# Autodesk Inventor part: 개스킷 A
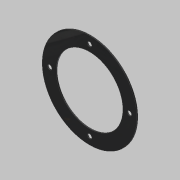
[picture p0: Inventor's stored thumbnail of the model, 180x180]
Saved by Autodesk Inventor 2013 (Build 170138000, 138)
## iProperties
Created: 2019-10
Part Number: 개스킷 A
Material: 고무
Document SubType Name: Modeling
Designer: mduedu
Density: 0.93 g/cm^3
Mass: 3.25402 g
Surface Area: 75.6338 cm^2
Volume: 3.49895 cm^3
Author: mduedu
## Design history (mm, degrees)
sketch "스케치1"
  geometry: C1 r 47.5 at (0, 0); C2 r 33.5 at (0, 0); 1 further point
  constraints: 2 centre point, 2 coincident
  dimensions: "d0" = 95 diameter of C1; "d1" = 67 diameter of C2
extrude "돌출1" new body sketch "스케치1" distance "d2" = 1; taper "d3" = 0 deg
sketch "스케치2" dims "d4" = 80
  geometry: C1 r 2.25 at (0, 40); 2 further points
  constraints: 2 vertical alignment, 1 centre point, 1 coincident, 2 other
  dimensions: "d5" = 4.5 diameter of C1
extrude "돌출2" cut sketch "스케치2" stored distance "d6" = 1; taper "d7" = 0 deg
node "솔리드1"
pattern_circular "원형 패턴1" dims angle "d9" = 360 deg
